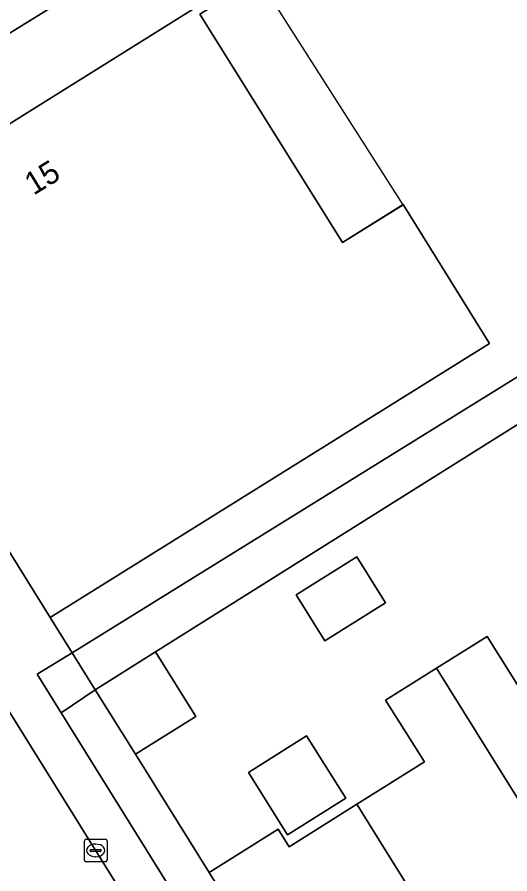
# Model space of a CAD drawing. Extents: x 159352 to 160617, y 385888 to 387323.
# Drawn here: x 159779.61 to 159801.42, y 385991.03 to 386028.96 of the extents above; entities that cross this region are included whole.
import ezdxf

# ---------------------------------------------------------------- set-up
doc = ezdxf.new("R2010")
doc.units = 0
for name, color, linetype in [('IMGEO_Erf', 7, 'Continuous'), ('IMGEO_Groenvoorziening', 7, 'Continuous'), ('IMGEO_Kolk', 7, 'Continuous'), ('IMGEO_Muur', 7, 'Continuous'), ('IMGEO_Pand', 7, 'Continuous'), ('IMGEO_Pand_nummerreeks', 7, 'Continuous'), ('IMGEO_Pand_overbouw', 7, 'Continuous'), ('IMGEO_Parkeervlak_open', 7, 'Continuous'), ('IMGEO_Rijbaan_lokaal_open', 7, 'Continuous'), ('IMGEO_Voetpad_open', 7, 'Continuous')]:
    doc.layers.add(name, color=color, linetype=linetype)

msp = doc.modelspace()

# ---------------------------------------------------------------- linework, layer by layer
at = {"layer": 'IMGEO_Erf'}
for points in [[(159787.689, 386029.088), (159794.008, 386018.98), (159796.689, 386020.663), (159800.515, 386014.52), (159781.076, 386002.383), (159782.041, 386000.826), (159811.303, 386018.953)], [(159812.211, 386017.488), (159785.725, 386000.86), (159787.515, 385998.007), (159784.847, 385996.333), (159788.109, 385991.097), (159791.159, 385993.01), (159791.648, 385992.231), (159794.649, 385994.113), (159797.637, 385995.987), (159795.916, 385998.731), (159798.162, 386000.14), (159800.406, 386001.547), (159803.461, 385996.676)]]:
    msp.add_lwpolyline(points, dxfattribs=at)
for points in [[(159795.918, 386003.03), (159793.22, 386001.35), (159791.953, 386003.384), (159794.648, 386005.068)], [(159794.151, 385994.382), (159791.573, 385992.766), (159789.841, 385995.528), (159792.418, 385997.145)]]:
    msp.add_lwpolyline(points, close=True, dxfattribs=at)
at = {"layer": 'IMGEO_Groenvoorziening'}
msp.add_lwpolyline([(159781.555, 385998.167), (159794.607, 385977.16), (159796.167, 385978.135), (159793.585, 385982.265), (159788.109, 385991.097), (159784.847, 385996.333), (159783.057, 385999.185)], close=True, dxfattribs=at)
at = {"layer": 'IMGEO_Kolk'}
for p, q in [((159782.584, 385991.645), (159782.584, 385992.497)), ((159782.659, 385992.571), (159783.511, 385992.571)), ((159783.072, 385992.351), (159783.097, 385992.351)), ((159783.585, 385992.497), (159783.585, 385991.645)), ((159782.843, 385992.065), (159782.843, 385992.077)), ((159783.281, 385992.028), (159782.883, 385992.028)), ((159782.886, 385992.114), (159783.284, 385992.114)), ((159783.327, 385992.077), (159783.327, 385992.065)), ((159783.095, 385991.791), (159783.07, 385991.791)), ((159783.511, 385991.571), (159782.659, 385991.571))]:
    msp.add_line(p, q, dxfattribs=at)
for points in [[(159782.584, 385991.645), (159782.584, 385992.497)], [(159782.659, 385992.571), (159783.511, 385992.571)], [(159783.585, 385992.497), (159783.585, 385991.645)], [(159783.511, 385991.571), (159782.659, 385991.571)]]:
    msp.add_lwpolyline(points, dxfattribs=at)
for centre, radius, start, end in [((159782.661, 385992.495), 0.0765, 91.552, 178.448), ((159782.661, 385992.495), 0.0765, 91.552, 178.448), ((159783.509, 385992.495), 0.0765, 1.552, 88.448), ((159783.509, 385992.495), 0.0765, 1.552, 88.448), ((159782.883, 385992.074), 0.0403, 85.8775, 175.7526), ((159782.88, 385992.064), 0.0366, 178.938, 274.7102), ((159783.284, 385992.071), 0.043, 264.8664, 352.4533), ((159783.288, 385992.076), 0.0386, 1.7309, 96.639), ((159782.661, 385991.647), 0.0765, 181.552, 268.448), ((159782.661, 385991.647), 0.0765, 181.552, 268.448), ((159783.509, 385991.647), 0.0765, 271.552, 358.448), ((159783.509, 385991.647), 0.0765, 271.552, 358.448)]:
    msp.add_arc(centre, radius, start, end, dxfattribs=at)
for centre, major_axis, ratio, start_param, end_param in [((159783.071, 385992.071), (-0.387, 0.002), 0.722429, 4.712389, 7.853982), ((159783.096, 385992.071), (-0.39, 0.002), 0.717154, 1.570796, 4.712389)]:
    msp.add_ellipse(centre, major_axis=major_axis, ratio=ratio, start_param=start_param, end_param=end_param, dxfattribs=at)
at = {"layer": 'IMGEO_Muur'}
msp.add_lwpolyline([(159784.847, 385996.333), (159788.109, 385991.097)], dxfattribs=at)
at = {"layer": 'IMGEO_Pand'}
for points in [[(159770.784, 386018.94), (159781.076, 386002.383), (159800.515, 386014.52), (159796.689, 386020.663), (159794.008, 386018.98), (159787.689, 386029.088), (159788.029, 386029.306), (159787.845, 386029.593)], [(159795.918, 386003.03), (159794.648, 386005.068), (159791.953, 386003.384), (159793.22, 386001.35)], [(159806.504, 385998.584), (159803.461, 385996.676), (159800.406, 386001.547), (159798.162, 386000.14), (159805.188, 385988.864), (159807.536, 385990.327), (159808.536, 385990.104), (159810.042, 385991.036), (159810.262, 385992.024), (159810.497, 385992.174)], [(159787.515, 385998.007), (159785.725, 386000.86), (159783.057, 385999.185), (159784.847, 385996.333)], [(159798.162, 386000.14), (159795.916, 385998.731), (159797.637, 385995.987), (159794.649, 385994.113), (159795.977, 385991.982), (159800.428, 385984.839), (159803.052, 385986.476), (159803.3, 385987.688), (159805.188, 385988.864)], [(159794.151, 385994.382), (159792.418, 385997.145), (159789.841, 385995.528), (159791.573, 385992.766)], [(159795.977, 385991.982), (159794.649, 385994.113), (159791.648, 385992.231), (159791.159, 385993.01), (159788.109, 385991.097), (159793.585, 385982.265), (159795.571, 385983.493), (159796.328, 385982.28), (159800.428, 385984.839)]]:
    msp.add_lwpolyline(points, close=True, dxfattribs=at)
at = {"layer": 'IMGEO_Pand_overbouw'}
msp.add_lwpolyline([(159790.097, 386030.999), (159787.845, 386029.593), (159788.029, 386029.306), (159787.689, 386029.088), (159794.008, 386018.98), (159796.694, 386020.655)], close=True, dxfattribs=at)
at = {"layer": 'IMGEO_Parkeervlak_open'}
msp.add_lwpolyline([(159772.944, 386024.359), (159792.613, 386036.48)], dxfattribs=at)
at = {"layer": 'IMGEO_Rijbaan_lokaal_open'}
msp.add_lwpolyline([(159762.791, 386015.603), (159788.248, 385974.74), (159788.6, 385974.171), (159792.653, 385976.684), (159779.143, 385998.41), (159766.946, 386018.026), (159766.892, 386018.124)], close=True, dxfattribs=at)
at = {"layer": 'IMGEO_Voetpad_open'}
for points in [[(159766.532, 386025.622), (159770.784, 386018.94), (159787.845, 386029.593), (159790.097, 386030.999), (159801.54, 386038.089), (159804.855, 386040.143), (159811.969, 386044.648)], [(159792.613, 386036.48), (159772.944, 386024.359)], [(159779.143, 385998.41), (159792.653, 385976.684), (159792.94, 385976.214), (159794.607, 385977.16), (159781.555, 385998.167), (159780.497, 385999.87), (159782.041, 386000.826), (159781.076, 386002.383), (159770.784, 386018.94), (159766.532, 386025.622)]]:
    msp.add_lwpolyline(points, dxfattribs=at)
for points in [[(159812.211, 386017.488), (159811.303, 386018.953), (159782.041, 386000.826), (159783.057, 385999.185), (159785.725, 386000.86)], [(159782.041, 386000.826), (159780.497, 385999.87), (159781.555, 385998.167), (159783.057, 385999.185)]]:
    msp.add_lwpolyline(points, close=True, dxfattribs=at)

# ---------------------------------------------------------------- texts
at = {"layer": 'IMGEO_Pand_nummerreeks'}
msp.add_text('15', height=1, rotation=31.7326, dxfattribs=at).set_placement((159780.338, 386021.055))

doc.saveas('drawing.dxf')
